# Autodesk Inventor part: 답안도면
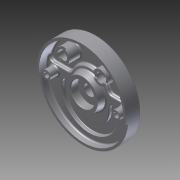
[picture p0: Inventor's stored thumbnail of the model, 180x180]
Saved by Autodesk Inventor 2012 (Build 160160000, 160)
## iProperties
Created: 2015-04
Part Number: 답안도면
Material: Default
Document SubType Name: Modeling
Designer: Owner
Mass: 401.386 g
Surface Area: 1039 cm^2
Volume: 401.386 cm^3
Density: 1 g/cm^3
Author: Owner
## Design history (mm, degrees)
sketch "스케치1"
  geometry: C1 r 95 at (0, 0); 1 further point
  constraints: 1 centre point, 1 coincident
  dimensions: "d0" = 190 diameter of C1
extrude "돌출1" new body sketch "스케치1" distance "d1" = 32; taper "d2" = 0 deg
sketch "스케치2"
  geometry: C1 r 95 at (0, 0) reference; C2 r 90 at (0, 0)
  constraints: 1 centre point, 1 coincident
  dimensions: "d3" = 180 diameter of C2
extrude "돌출2" cut sketch "스케치2" distance "d4" = 18; taper "d5" = 0 deg
sketch "스케치3"
  geometry: L1 (90, 14)-(-90, 14) reference; L2 (0, 0)-(0, 65.515); L3 (-35, 14)-(-32.355, 29); L4 (-32.355, 29)-(0, 29); L5 (-35, 14)-(0, 14)
  constraints: 8 end point, 3 point on line, 1 midpoint, 1 parallel, 1 perpendicular
  dimensions: "d6" = 100 deg angle of L1 L3; "d7" = 15 distance between parallel lines of L4 L1; "d8" = 70 diameter of L3.start L2
revolve "회전1" sketch "스케치3" stored, may be unused: angle "d9" = 90 deg
sketch "스케치4"
  geometry: L1 (-89.196, 12)-(-40.249, 12); L2 (40.249, 12)-(89.196, 12); C1 r 35 at (0, 0) reference; A1 r 42 centre (0, 0) between (40.249, 12) and (-40.249, 12); A2 r 90 centre (0, 0) between (89.196, 12) and (-89.196, 12); 2 further points
  constraints: 4 end point, 4 point on circle, 2 centre point, 2 coincident, 2 horizontal, 1 horizontal alignment, 1 vertical alignment, 2 other
  dimensions: "d11" = 84 diameter of A1; "d110" = 12 distance from line of C1.centre L2
extrude "돌출4" cut sketch "스케치4" distance "d15" = 7; taper "d16" = 0 deg
hole "구멍1" diameter "d19" = 23; stored, may be unused: countersink angle "d23" = 90 deg, drill point angle "d25" = 118 deg; dims "d17" = 10, "d18" = 10, "d20" = 6, "d21" = 50, "d22" = 15, "d24" = 8
sketch "스케치5"
  geometry: L1 (89.658, -7.844)-(94.638, -8.28); L2 (-89.658, -7.844)-(-94.638, -8.28); L3 (-89.658, -7.844)-(0, 0); L4 (0, 0)-(89.658, -7.844); L5 (-40.249, 12)-(-89.196, 12) reference; L6 (89.196, 12)-(40.249, 12) reference; A1 r 90 centre (0, 0) between (-89.658, -7.844) and (89.658, -7.844) reference; A2 r 95 centre (0, 0) between (94.638, -8.28) and (-94.638, -8.28) reference
  constraints: 8 end point, 4 point on circle, 2 collinear
  dimensions: "d111" = 5 deg angle of L3 L5; "d112" = 5 deg angle of L4 L6
extrude "돌출5" cut sketch "스케치5" distance "d29" = 5; taper "d30" = 0 deg
sketch "스케치6"
  geometry: L1 (-99.192, -19)-(99.192, -19); L2 (-99.192, -14)-(99.192, -14); L3 (41, -19)-(41, -14); L4 (59, -19)-(59, -14); L5 (-41, -19)-(-41, -14); L6 (-59, -19)-(-59, -14); A1 r 90 centre (0, 0) between (-89.196, 12) and (89.196, 12) reference; A2 r 9 centre (50, -14) between (59, -14) and (41, -14); A3 r 9 centre (-50, -14) between (-41, -14) and (-59, -14); A4 r 59 centre (0, -19) between (-59, -19) and (59, -19); A5 r 41 centre (0, -19) between (-41, -19) and (41, -19); 3 further points
  constraints: 12 end point, 8 point on circle, 7 point on line, 6 parallel, 5 tangent, 4 centre point, 2 coincident, 2 midpoint, 2 vertical alignment, 1 equal radius, 1 perpendicular
  dimensions: "d45" = 5 distance between parallel lines of L1 L2; "d47" = 18 distance between parallel lines of L4 L3; "d48" = 41 radius of A5; "d113" = 19 distance from line of L1 A1.centre
extrude "돌출6" cut sketch "스케치6" distance "d49" = 7; taper "d50" = 0 deg
sketch "스케치8"
  geometry: C1 r 11.5 at (0, 0) reference; C2 r 9 at (74, 0)
  constraints: 1 centre point, 1 horizontal alignment
  dimensions: "d53" = 18 diameter of C2; "d54" = 74 distance of C2.centre C1.centre
extrude "돌출7" join sketch "스케치8" stored distance "d55" = 7; taper "d56" = 0 deg
sketch "스케치9"
  geometry: C1 r 11.5 at (0, 0) reference; 1 further point
  constraints: 1 horizontal alignment
  dimensions: "d57" = 74 distance of point (74, 0) C1.centre
hole "구멍2" sketch "스케치9" at (74, 0) diameter "d58" = 11; stored, may be unused: countersink angle "d62" = 90 deg, drill point angle "d64" = 118 deg; dims "d59" = 6, "d60" = 18, "d61" = 11, "d63" = 8
sketch "스케치10"
  geometry: C1 r 11.5 at (0, 0) reference; C2 r 15 at (-40, 52)
  constraints: 1 centre point
  dimensions: "d65" = 30 diameter of C2; "d66" = 52 vertical distance of C1.centre C2.centre; "d67" = 40 horizontal distance of C1.centre C2.centre
extrude "돌출8" join sketch "스케치10" stored distance "d68" = 7; taper "d69" = 0 deg
hole "구멍3" diameter "d72" = 20; stored, may be unused: countersink angle "d76" = 90 deg, drill point angle "d78" = 118 deg; dims "d70" = 10, "d71" = 10, "d73" = 6, "d74" = 18, "d75" = 11, "d77" = 8
sketch "스케치11"
  geometry: L1 (-6, 13.748)-(-6, 8); L2 (-6, -8)-(-6, -13.748); L3 (6, 13.748)-(6, 8); L4 (6, -8)-(6, -13.748); A1 r 10 centre (0, 0) between (-6, 8) and (-6, -8) reference; A2 r 15 centre (0, 0) between (-6, 13.748) and (-6, -13.748) reference; 1 further point
  constraints: 8 end point, 8 point on circle, 6 parallel, 2 vertical
  dimensions: "d80" = 12 distance between parallel lines of L3 L1; "d81" = 12 distance between parallel lines of L4 L2
extrude "돌출9" cut sketch "스케치11" distance "d82" = 3; taper "d83" = 0 deg
sketch "스케치12"
  geometry: L1 (-13.748, 6)-(-8, 6); L2 (8, 6)-(13.748, 6); L3 (-13.748, -6)-(-8, -6); L4 (8, -6)-(13.748, -6); A1 r 10 centre (0, 0) between (-8, 6) and (8, 6) reference; A2 r 15 centre (0, 0) between (-13.748, -6) and (13.748, -6) reference; 1 further point
  constraints: 8 end point, 8 point on circle, 6 parallel, 2 horizontal
  dimensions: "d84" = 12 distance between parallel lines of L3 L1; "d85" = 12 distance between parallel lines of L4 L2
extrude "돌출10" cut sketch "스케치12" distance "d86" = 3; taper "d87" = 0 deg
sketch "스케치13"
  geometry: L1 (36.062, -36.062)-(50.912, -50.912); L2 (-36.062, -36.062)-(-50.912, -50.912); L3 (-36.062, -36.062)-(0, 0); L4 (0, 0)-(36.062, -36.062); C1 r 11.5 at (0, 0) reference; C2 r 95 at (0, 0) reference; A1 r 51 centre (0, 0) between (-36.062, -36.062) and (36.062, -36.062); A2 r 72 centre (0, 0) between (-50.912, -50.912) and (50.912, -50.912); 1 further point
  constraints: 8 end point, 5 point on circle, 3 coincident, 2 centre point, 1 collinear, 1 perpendicular, 1 vertical alignment
  dimensions: "d91" = 90 deg angle of L1 L2; "d92" = 72 radius of A2; "d93" = 51 radius of A1
extrude "돌출11" join sketch "스케치13" distance "d94" = 5; taper "d95" = 0 deg
fillet "모깎기1" dims "d98" = 5
chamfer "모따기1" distance "d101" = 1; stored, may be unused: second distance "d102" = 2, angle "d103" = 45 deg
fillet "모깎기4" dims "d104" = 3
fillet "모깎기5" dims "d105" = 5
fillet "모깎기6" dims "d106" = 1
fillet "모깎기7" dims "d114" = 10
fillet "모깎기8" dims "d115" = 3
fillet "모깎기9" dims "d116" = 3
fillet "모깎기10" dims "d117" = 3
sketch "스케치15"
  geometry: 1 further point
node "작업 평면2"
sketch "스케치16"
  geometry: 2 further points
  constraints: 1 vertical alignment, 1 other
feature "엠보싱1" sketch "스케치16" dims "d119" = 0.5, "d120" = 0
fillet "모깎기11" dims "d121" = 3
node "솔리드1"
mirror "대칭1"
mirror "대칭2"
other parameters: "d10" = 12, "d32" = 118, "d33" = 19, "d43" = 82, "d44" = 118, "d79" = 12, "d89" = 144, "d90" = 90 deg, "d109" = 12
